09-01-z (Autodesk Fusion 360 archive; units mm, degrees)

design "09-01-z" references "09-01-KOTEI"
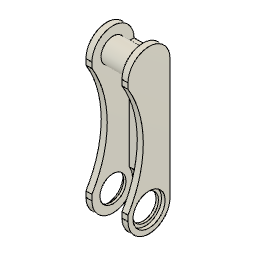
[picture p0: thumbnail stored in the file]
component_insert "コンポーネントの挿入"
ground "固定"

design "09-01-KOTEI"
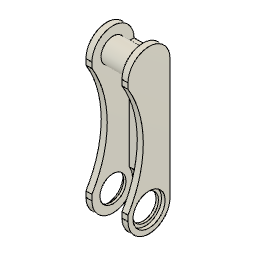
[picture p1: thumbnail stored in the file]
sketch "スケッチ1" plane through (0, 0, 0) normal (1, 0, 0) x axis (0, 0, -1)
  circle C1 centre (0, 40) radius 4
  point P1 (0, 0)
  point P2 (0, 40)
  vertical P1 P2
  dimension "d1" diameter C1 = 8
  dimension "d29" distance P1 P2 = 40
extrude "押し出し1" new body sketch "スケッチ1" + "スケッチ5" profile of S1:C1 distance 10
sketch "スケッチ2" plane through (5, 0, 0) normal (1, 0, 0) x axis (0, 0, -1)
  line L1 (-7, 0) -> (-7, 40)
  line L2 (7, 40) -> (7, 0)
  line L3 (0, 0) -> (0, 40)
  circle C1 centre (0, 40) radius 4
  arc A1 centre (0, 0) radius 7 clockwise from (7, 0) to (-7, 0)
  arc A2 centre (0, 40) radius 7 clockwise from (-7, 40) to (7, 40)
  point P7 (0, 40)
  point P9 (0, 40)
  point P8 (0, 0)
  tangent L1 A1
  tangent A1 L2
  parallel L1 L2
  tangent L2 A2
  tangent L1 A2
  vertical L3
  coincident P7 P9
  concentric C1 A2
  dimension "d4" radius A2 = 7
  dimension "d5" distance P7 P8 = 40
extrude "押し出し2" add sketch "スケッチ2" profile of C1 L1 A1 L2 A2 along normal blind 2
mirror "ミラー" sketch "スケッチ5" mirrorStitchTolerance 0.1
sketch "スケッチ3" plane through (0, 0, 0) normal (1, 0, 0) x axis (0, 0, -1)
  line L1 (7, 40) -> (5.4, 40)
  line L2 (7, 0) -> (7, 40)
  line L3 (5.4, 0) -> (7, 0)
  line L4 (5.4, 40) -> (5.4, 0)
  point P3 (7, 40)
  point P6 (7, 40)
  point P4 (7, 0)
  point P7 (7, 0)
  horizontal L1
  vertical L2
  horizontal L3
  vertical L4
  coincident P3 P6
  coincident P4 P7
  dimension "d10" distance L2 L4 = 1.6
extrude "押し出し3" add sketch "スケッチ3" distance 10
sketch "スケッチ4" plane through (0, 0, 0) normal (1, 0, 0) x axis (0, 0, -1)
  circle C1 centre (-36.9324, 20) radius 35
  arc A1 centre (0, 40) radius 7 clockwise from (-7, 40) to (7, 40)
  arc A2 centre (0, 0) radius 7 clockwise from (7, 0) to (-7, 0)
  tangent C1 A1
  tangent C1 A2
  dimension "d13" diameter C1 = 70
extrude "押し出し4" cut sketch "スケッチ4" profile of C1 no distance stored
sketch "スケッチ5" plane through (0, 0, 0) normal (1, 0, 0) x axis (0, 0, -1)
  circle C1 centre (0, 0) radius 6.5
  arc A1 centre (0, 0) radius 7 clockwise from (7, 0) to (-7, 0)
  concentric C1 A1
  dimension "d15" diameter C1 = 13
extrude "押し出し5" cut sketch "スケッチ5" profile of C1 distance 10
chamfer "面取り" distance 0.2
hole "穴1" HoleDepth 2 HoleDiameter 8.7 TipAngle 118 CBDepth 1.2 CBDiameter 10.7
hole "穴2" HoleDepth 2 HoleDiameter 8.7 TipAngle 118 CBDepth 1.2 CBDiameter 10.7
joint_origin "JointOrigin1" sketch "スケッチ5" OffsetX 0 OffsetY 0 OffsetZ 0 AngleZ 0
